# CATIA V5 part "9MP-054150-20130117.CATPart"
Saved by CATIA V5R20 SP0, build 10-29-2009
Part number: 9MP-054150-20130117
Revision: ANY
Definition: UNKNOWN
Nomenclature: 9MP-054150-20130117
Source: Unknown
Bounding box of the stored display mesh (mm): x 1030.802 to 1180.779, y 1552.793 to 1559.247, z 0 to 5
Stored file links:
  C:\Users\Utente\Desktop\IO LAVORO\3D X SITO CF\CUMSA\3D files PF\PF 054150\9MP-054150-20130117.CATPart
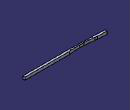
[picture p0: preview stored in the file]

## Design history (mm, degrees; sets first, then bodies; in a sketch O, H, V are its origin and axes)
Body1 "Cortar-Extruir1" (main body)
  Solid1: solid without history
